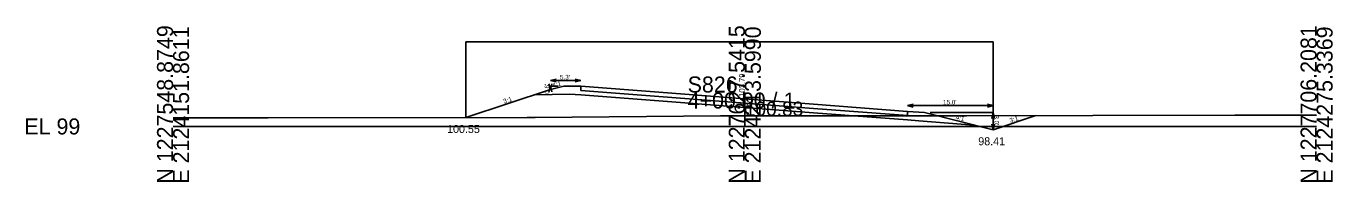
# Model space of a CAD drawing. Extents: x 2118382 to 2129610, y 1213030 to 1222578.
# Drawn here: x 2118381.9 to 2118610.4, y 1214530.1 to 1214557.3 of the extents above; entities that cross this region are included whole.
import ezdxf

# ---------------------------------------------------------------- set-up
doc = ezdxf.new("R2010")
doc.units = 0
for name, color, linetype in [('XS_CELL', 7, 'Continuous'), ('XS_M_DITCH', 7, 'Continuous'), ('XS_P_FINISHED_GRADE', 7, 'Continuous'), ('XS_P_FINISHED_GRADE_ELEV_TX', 7, 'Continuous'), ('XS_P_SUBGRADE_GRANULAR', 7, 'Continuous'), ('XS_P_SUBGRADE_PAVEMENT', 7, 'Continuous'), ('XS_P_TX_CLEARZONE', 7, 'Continuous'), ('XS_P_TX_DCH', 7, 'Continuous'), ('XS_P_TX_FS_BS', 7, 'Continuous'), ('XS_X_GROUND', 7, 'Continuous'), ('XS_X_GROUND_TX', 7, 'Continuous')]:
    doc.layers.add(name, color=color, linetype=linetype)

msp = doc.modelspace()

# ---------------------------------------------------------------- linework, layer by layer
at = {"layer": 'XS_CELL'}
for p, q in [((2118507.6, 1214539.8), (2118507.6, 1214545.73)), ((2118407.6, 1214539.8), (2118507.6, 1214539.8)), ((2118507.6, 1214539.8), (2118607.6, 1214539.8))]:
    msp.add_line(p, q, dxfattribs=at)
at = {"layer": 'XS_M_DITCH'}
for p, q in [((2118458.83, 1214541.35), (2118458.83, 1214554.6)), ((2118458.83, 1214554.6), (2118551.04, 1214554.6)), ((2118551.04, 1214554.6), (2118551.04, 1214539.21))]:
    msp.add_line(p, q, dxfattribs=at)
at = {"layer": 'XS_P_FINISHED_GRADE'}
for p, q in [((2118473.6, 1214546.27), (2118458.83, 1214541.35)), ((2118475.93, 1214546.85), (2118473.6, 1214546.27)), ((2118478.93, 1214546.82), (2118475.93, 1214546.85)), ((2118495.6, 1214545.53), (2118478.93, 1214546.82)), ((2118495.6, 1214545.53), (2118507.6, 1214544.6)), ((2118507.6, 1214544.6), (2118519.6, 1214543.69)), ((2118519.6, 1214543.69), (2118536.03, 1214542.44)), ((2118536.03, 1214542.44), (2118539.03, 1214542.21)), ((2118539.03, 1214542.21), (2118551.04, 1214539.21)), ((2118551.04, 1214539.21), (2118558.5, 1214541.7))]:
    msp.add_line(p, q, dxfattribs=at)
at = {"layer": 'XS_P_SUBGRADE_GRANULAR'}
for p, q in [((2118476.93, 1214545.47), (2118470.85, 1214545.35)), ((2118478.93, 1214545.32), (2118476.93, 1214545.47)), ((2118495.6, 1214544.03), (2118478.93, 1214545.32)), ((2118495.6, 1214544.03), (2118507.6, 1214543.1)), ((2118507.6, 1214543.1), (2118519.6, 1214542.19)), ((2118519.6, 1214542.19), (2118536.03, 1214540.94)), ((2118536.03, 1214540.94), (2118538.03, 1214540.79)), ((2118538.03, 1214540.79), (2118547.66, 1214540.05))]:
    msp.add_line(p, q, dxfattribs=at)
at = {"layer": 'XS_P_SUBGRADE_PAVEMENT'}
for p, q in [((2118478.93, 1214546.07), (2118478.93, 1214546.82)), ((2118495.6, 1214544.78), (2118478.93, 1214546.07)), ((2118495.6, 1214544.78), (2118507.6, 1214543.85)), ((2118507.6, 1214543.85), (2118519.6, 1214542.94)), ((2118519.6, 1214542.94), (2118536.03, 1214541.69)), ((2118536.03, 1214541.69), (2118536.03, 1214542.44))]:
    msp.add_line(p, q, dxfattribs=at)
at = {"layer": 'XS_P_TX_CLEARZONE'}
for p, q in [((2118473.6, 1214547.82), (2118474.6, 1214548.07)), ((2118478.93, 1214547.82), (2118477.93, 1214548.07)), ((2118473.6, 1214546.27), (2118473.35, 1214547.27)), ((2118473.6, 1214546.85), (2118473.35, 1214545.85)), ((2118473.6, 1214547.82), (2118474.6, 1214547.57)), ((2118478.93, 1214547.82), (2118473.6, 1214547.82)), ((2118473.6, 1214546.27), (2118473.85, 1214547.27)), ((2118473.6, 1214546.85), (2118473.85, 1214545.85)), ((2118473.6, 1214546.85), (2118473.6, 1214546.27)), ((2118474.93, 1214546.85), (2118473.6, 1214546.85)), ((2118478.93, 1214547.82), (2118477.93, 1214547.57)), ((2118536.03, 1214543.44), (2118537.03, 1214543.69)), ((2118536.03, 1214543.44), (2118537.03, 1214543.19)), ((2118536.03, 1214543.44), (2118551.04, 1214543.44)), ((2118551.04, 1214543.44), (2118550.04, 1214543.69)), ((2118551.04, 1214543.44), (2118550.04, 1214543.19)), ((2118540.03, 1214542.21), (2118551.04, 1214542.21)), ((2118551.04, 1214542.21), (2118550.79, 1214541.21)), ((2118551.04, 1214542.21), (2118551.04, 1214539.21)), ((2118551.04, 1214542.21), (2118551.29, 1214541.21)), ((2118551.04, 1214539.21), (2118550.79, 1214540.21)), ((2118551.04, 1214539.21), (2118551.29, 1214540.21))]:
    msp.add_line(p, q, dxfattribs=at)
at = {"layer": 'XS_X_GROUND'}
for p, q in [((2118407.6, 1214541.28), (2118419.2, 1214541.3)), ((2118419.2, 1214541.3), (2118424.22, 1214541.28)), ((2118424.22, 1214541.28), (2118469.53, 1214541.37)), ((2118469.53, 1214541.37), (2118469.99, 1214541.37)), ((2118469.99, 1214541.37), (2118470.58, 1214541.37)), ((2118470.58, 1214541.37), (2118470.95, 1214541.37)), ((2118470.95, 1214541.37), (2118503.37, 1214541.63)), ((2118503.37, 1214541.63), (2118507.6, 1214541.64)), ((2118507.6, 1214541.64), (2118536.62, 1214541.67)), ((2118536.62, 1214541.67), (2118546.38, 1214541.64)), ((2118546.38, 1214541.64), (2118568.45, 1214541.74)), ((2118568.45, 1214541.74), (2118593.31, 1214541.75)), ((2118593.31, 1214541.75), (2118601.84, 1214541.78)), ((2118601.84, 1214541.78), (2118607.6, 1214541.78))]:
    msp.add_line(p, q, dxfattribs=at)

# ---------------------------------------------------------------- texts
at = {"layer": 'XS_CELL'}
for s, p in [('N 1227548.8749', (2118407.6, 1214529.8)), ('E 2124151.8611', (2118410.4, 1214529.8)), ('N 1227627.5415', (2118507.6, 1214529.8)), ('E 2124213.5990', (2118510.4, 1214529.8)), ('N 1227706.2081', (2118607.6, 1214529.8)), ('E 2124275.3369', (2118610.4, 1214529.8))]:
    msp.add_text(s, height=2.8, rotation=90, dxfattribs=at).set_placement(p)
for s, p in [('S826', (2118497.6, 1214545.73)), ('4+00.00 / 1', (2118497.6, 1214542.93)), ('EL 99', (2118381.6, 1214538.4))]:
    msp.add_text(s, height=2.8, dxfattribs=at).set_placement(p)
at = {"layer": 'XS_P_FINISHED_GRADE_ELEV_TX'}
msp.add_text(' 103.79', height=1, rotation=90, dxfattribs=at).set_placement((2118507.6, 1214544.6))
at = {"layer": 'XS_P_TX_CLEARZONE'}
for s, p in [("5.3'", (2118475.27, 1214548.02)), ("15.0'", (2118542.26, 1214543.64))]:
    msp.add_text(s, height=0.8, dxfattribs=at).set_placement(p)
for s, rotation, p in [("0.6'", 90, (2118473.4, 1214545.51)), ("3.0'", 270, (2118551.24, 1214541.74))]:
    msp.add_text(s, height=0.8, rotation=rotation, dxfattribs=at).set_placement(p)
at = {"layer": 'XS_P_TX_DCH'}
for s, p in [('100.55', (2118455.53, 1214538.65)), ('98.41', (2118548.43, 1214536.51))]:
    msp.add_text(s, height=1.4, dxfattribs=at).set_placement(p)
at = {"layer": 'XS_P_TX_FS_BS'}
for s, rotation, p in [('4:1', 14.025, (2118474.06, 1214546.59)), ('3:1', 18.4206, (2118465.51, 1214543.78)), ('4:1', 345.9775, (2118544.42, 1214541.07)), ('3:1', 18.4174, (2118554.06, 1214540.43))]:
    msp.add_text(s, height=0.8, rotation=rotation, dxfattribs=at).set_placement(p)
at = {"layer": 'XS_X_GROUND_TX'}
msp.add_text('100.83', height=2.5, dxfattribs=at).set_placement((2118507.6, 1214541.64))

doc.saveas('drawing.dxf')
